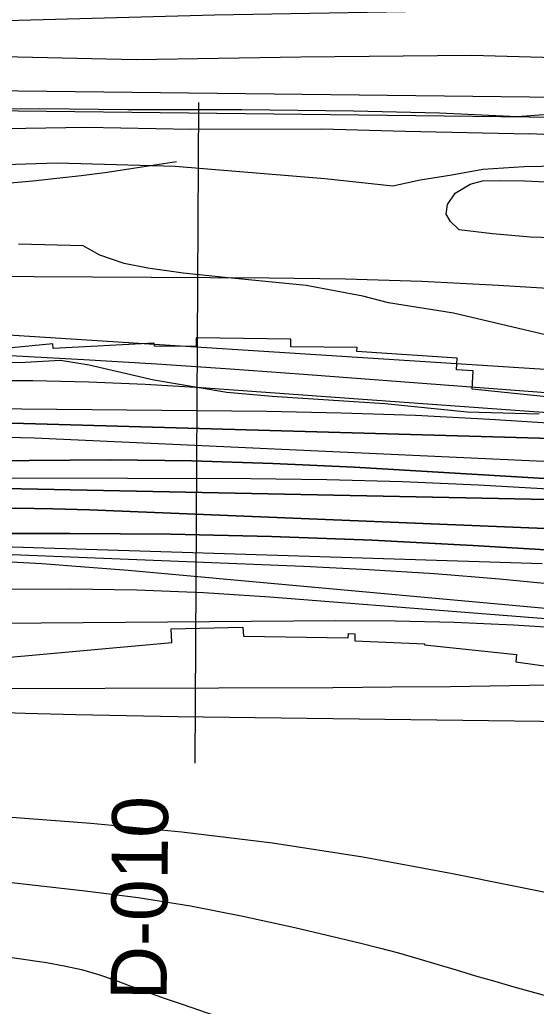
# Model space of a CAD drawing. Extents: x 3477039 to 3515015, y 546746 to 572297.
# Drawn here: x 3495218 to 3495983, y 565048 to 566511 of the extents above; entities that cross this region are included whole.
import ezdxf

# ---------------------------------------------------------------- set-up
doc = ezdxf.new("R2010")
doc.units = 0
for name, color, linetype in [('V-FLOD-BASE', 7, 'Continuous'), ('V-LEVE-TOET', 7, 'Continuous'), ('V-RIVR-EDGE', 7, 'Continuous'), ('V-RIVR-RANG', 7, 'Continuous'), ('V-RIVR-RANG-IDEN', 7, 'Continuous'), ('V-ROAD-CNTR', 7, 'Continuous'), ('V-RRAP-RVMT', 7, 'Continuous'), ('V-SITE-VEGE', 7, 'Continuous'), ('V-SURV-LINE', 7, 'Continuous'), ('V-TOPO-DPTH', 7, 'Continuous'), ('V-TOPO-MAJR', 7, 'Continuous'), ('V-TOPO-MINR', 7, 'Continuous'), ('V-TOPO-WATR', 7, 'Continuous'), ('V-WETL-SWMP', 7, 'Continuous')]:
    doc.layers.add(name, color=color, linetype=linetype)

msp = doc.modelspace()

# ---------------------------------------------------------------- linework, layer by layer
at = {"layer": 'V-FLOD-BASE'}
msp.add_lwpolyline([(3494639.8, 566308.8), (3494681.3, 566333.5), (3494743, 566352.4), (3494831.7, 566366.4), (3494856.4, 566368), (3494919.1, 566360.5), (3494977.8, 566353.6), (3495010.6, 566356.3), (3495078.7, 566362.8), (3495149.8, 566373.4), (3495191.5, 566378.4), (3495247.3, 566379.2), (3495377.5, 566377.6), (3495546.5, 566377.5), (3495712, 566375.7), (3495839.3, 566372.4), (3495954.2, 566367.4), (3496006.8, 566370.9)], dxfattribs=at)
at = {"layer": 'V-LEVE-TOET'}
for points in [[(3496080.2, 566452), (3495886.6, 566457.5), (3495633.7, 566455.3), (3495390.2, 566451.3), (3495170.2, 566456.4), (3495035.8, 566458), (3494947.5, 566457), (3494877.4, 566456.3), (3494775.8, 566444.7), (3494565.5, 566414.6), (3494406.3, 566389.4), (3494203.1, 566361), (3494009.2, 566332.5), (3493874.7, 566309.4), (3493682, 566282.1), (3493457.7, 566250.4), (3493368.4, 566234.6), (3493294.9, 566215.2), (3493192.5, 566183.7)], [(3494244.5, 566253.3), (3494443.1, 566285.8), (3494583.4, 566301.2), (3494606.6, 566302.1), (3494645.7, 566303.7), (3494796.6, 566327.2), (3494845.4, 566333.9), (3494861.8, 566335.5), (3494892.9, 566332.9), (3494949.8, 566323.7), (3494973.8, 566320), (3495001.9, 566318.6), (3495068.3, 566328.1), (3495147.1, 566343.9), (3495170, 566346.7), (3495197, 566349.4), (3495315.5, 566351.5), (3495471, 566348.6), (3495664.6, 566348.9), (3495788.4, 566345.6), (3495972.6, 566341.6)], [(3496555.2, 566271.5), (3496535.5, 566269.3), (3496507.6, 566281.7), (3496474.5, 566296.9), (3496443.6, 566306.7), (3496386.4, 566320.4), (3496328.7, 566329.3), (3496256, 566335.1), (3496175.8, 566338.2), (3496118.1, 566340.7), (3496026.1, 566339.1), (3495972.6, 566341.6)]]:
    msp.add_lwpolyline(points, dxfattribs=at)
at = {"layer": 'V-RIVR-EDGE'}
msp.add_lwpolyline([(3495987, 565925.7), (3495880.4, 565928.5), (3495758.5, 565941), (3495591.3, 565951.8), (3495524.5, 565958.1), (3495416.1, 565976.2), (3495320.5, 565998.5), (3495277.7, 566005.3), (3495225.6, 566002.4), (3495145.9, 566001.4), (3495072.4, 565991.7), (3495002.5, 565983.9), (3494900.7, 565962.7), (3494814.9, 565956.8), (3494768.9, 565943.5), (3494694.8, 565951.6), (3494618.8, 565945.7), (3494578.3, 565921.9), (3494528.1, 565909.7), (3494463.1, 565920.3), (3494433.1, 565913.7), (3494362.5, 565870.9), (3494346.6, 565853.8)], dxfattribs=at)
at = {"layer": 'V-RIVR-RANG'}
msp.add_line((3495482.1, 566388.1), (3495477.1, 565408.1), dxfattribs=at)
at = {"layer": 'V-ROAD-CNTR'}
msp.add_lwpolyline([(3495902.1, 566524.5), (3495505.9, 566517.2), (3495124.7, 566506.9)], dxfattribs=at)
msp.add_lwpolyline([(3495902.1, 566524.5), (3495505.9, 566517.2), (3495124.7, 566506.9)], dxfattribs=at)
at = {"layer": 'V-RRAP-RVMT'}
for points in [[(3496012.1, 565950), (3495887.9, 565962.9), (3495889.1, 565990.2), (3495864.4, 565991.5), (3495865.3, 566008.6), (3495717, 566018.9), (3495717.3, 566024.7), (3495619.1, 566025.4), (3495618.9, 566037), (3495478.8, 566039), (3495478.7, 566026.3), (3495417, 566026.7), (3495416.9, 566031), (3495267.1, 566023.3), (3495266.6, 566030), (3495108.1, 566014.8)], [(3494330.6, 565424.6), (3494453.9, 565441.3), (3494460.1, 565408.4), (3494623, 565435.5), (3494622.5, 565441.1), (3494845.3, 565474.4), (3494845.1, 565483), (3495029.1, 565505.9), (3495024.3, 565557.7), (3495146.4, 565573.9), (3495147.9, 565560.7), (3495442.6, 565587.3), (3495441.7, 565607.6), (3495547.8, 565610), (3495549.1, 565596.7), (3495704, 565594.1), (3495704.5, 565600.4), (3495714.1, 565600), (3495713.8, 565589.7), (3495817.2, 565585)], [(3495817.2, 565585), (3495817, 565583.5), (3495953.6, 565569.2), (3495952.4, 565558.6), (3496110.6, 565536.2)]]:
    msp.add_lwpolyline(points, dxfattribs=at)
at = {"layer": 'V-SITE-VEGE'}
for points in [[(3495164.3, 566295.2), (3495273.1, 566298.5), (3495447.7, 566293.7), (3495669.3, 566275), (3495770.2, 566264.5), (3495810.5, 566273.1), (3495857.6, 566280.7), (3495903.7, 566289.2), (3495964.6, 566292.8), (3496044, 566294.3)], [(3496006.9, 566040.7), (3495860.1, 566075.3), (3495763.8, 566090.8), (3495725.7, 566101), (3495641.7, 566116.4), (3495516.5, 566129.1), (3495459.5, 566134.8), (3495407.2, 566142.2), (3495372, 566149), (3495336.2, 566161.6), (3495311.6, 566175.3), (3495215.7, 566177.8)]]:
    msp.add_lwpolyline(points, dxfattribs=at)
at = {"layer": 'V-SURV-LINE'}
for points in [[(3494962.7, 566408.2), (3496182.8, 566393.8)], [(3496182.5, 566363.8), (3494962.3, 566378.2)]]:
    msp.add_lwpolyline(points, dxfattribs=at)
at = {"layer": 'V-TOPO-DPTH'}
for points in [[(3496218.5, 565911.7), (3495486.1, 565964.9), (3495403.1, 565969.9), (3495320.1, 565973.4), (3495237.1, 565975), (3495154, 565975.1), (3495049.9, 565974), (3495018.8, 565973.1), (3494987.8, 565971.6), (3494956.8, 565969), (3494925.9, 565965.8), (3494648.9, 565931.8), (3494499.1, 565912.1), (3494349.5, 565890.6)], [(3496230.7, 565883.3), (3494996.7, 565918.6), (3494992.9, 565918.7), (3494989, 565918.6), (3494985.2, 565918.4), (3494981.3, 565918.2), (3494928, 565913.4), (3494897.5, 565910.4), (3494867, 565907), (3494836.7, 565902.9), (3494806.4, 565898.3), (3494778.8, 565893.9), (3494734.8, 565886.8), (3494690.7, 565879.9), (3494646.6, 565873.1), (3494602.5, 565866.3), (3494256.1, 565814.1)], [(3494256.1, 565814.1), (3494602.5, 565866.3), (3494646.6, 565873.1), (3494690.7, 565879.9), (3494734.8, 565886.8), (3494778.8, 565893.9), (3494806.4, 565898.3), (3494836.7, 565902.9), (3494867, 565907), (3494897.5, 565910.4), (3494928, 565913.4), (3494981.3, 565918.2), (3494985.2, 565918.4), (3494989, 565918.6), (3494992.9, 565918.7), (3494996.7, 565918.6), (3496230.7, 565883.3)], [(3496202.8, 565817.8), (3495712.9, 565847), (3495592.6, 565852.7), (3495472.3, 565856.7), (3495351.9, 565857.9), (3495231.5, 565857.3), (3495032.8, 565854), (3495011.8, 565853.4), (3494990.7, 565852.4), (3494969.7, 565850.9), (3494948.7, 565849), (3494727.1, 565825.8), (3494595.5, 565811.1), (3494464, 565795.1), (3494332.8, 565777.2)], [(3494332.8, 565777.2), (3494464, 565795.1), (3494595.5, 565811.1), (3494727.1, 565825.8), (3494948.7, 565849), (3494969.7, 565850.9), (3494990.7, 565852.4), (3495011.8, 565853.4), (3495032.8, 565854), (3495231.5, 565857.3), (3495351.9, 565857.9), (3495472.3, 565856.7), (3495592.6, 565852.7), (3495712.9, 565847), (3496202.8, 565817.8)], [(3494307.6, 565736.5), (3494416.3, 565750.6), (3494525.1, 565764.8), (3494633.9, 565779.1), (3494781.7, 565798.6), (3494816.5, 565802.9), (3494851.5, 565806.9), (3494886.4, 565810.5), (3494921.4, 565813.7), (3494983.1, 565818.9), (3494987.3, 565819.2), (3494991.5, 565819.4), (3494995.7, 565819.5), (3494999.9, 565819.4), (3496024.1, 565798.6)], [(3494307.6, 565736.5), (3494416.3, 565750.6), (3494525.1, 565764.8), (3494633.9, 565779.1), (3494781.7, 565798.6), (3494816.5, 565802.9), (3494851.5, 565806.9), (3494886.4, 565810.5), (3494921.4, 565813.7), (3494983.1, 565818.9), (3494987.3, 565819.2), (3494991.5, 565819.4), (3494995.7, 565819.5), (3494999.9, 565819.4), (3496024.1, 565798.6)], [(3496164.7, 565749.3), (3495321.1, 565783.9), (3495266.4, 565785.5), (3495211.6, 565786.3), (3495156.8, 565785.8), (3495102, 565784.5), (3495061.9, 565783.1), (3495027.2, 565781.5), (3494992.5, 565779.4), (3494957.9, 565776.6), (3494923.4, 565773.3), (3494346.6, 565711.7), (3494251.7, 565700.5), (3494156.9, 565688.1), (3494062.4, 565673.7), (3493968, 565658.1), (3493820.9, 565632.1), (3493800.3, 565628.2), (3493779.8, 565623.9), (3493759.5, 565619.1), (3493739.2, 565613.9), (3493100.5, 565400)], [(3493100.5, 565400), (3493739.2, 565613.9), (3493759.5, 565619.1), (3493779.8, 565623.9), (3493800.3, 565628.2), (3493820.9, 565632.1), (3493968, 565658.1), (3494062.4, 565673.7), (3494156.9, 565688.1), (3494251.7, 565700.5), (3494346.6, 565711.7), (3494923.4, 565773.3), (3494957.9, 565776.6), (3494992.5, 565779.4), (3495027.2, 565781.5), (3495061.9, 565783.1), (3495102, 565784.5), (3495156.8, 565785.8), (3495211.6, 565786.3), (3495266.4, 565785.5), (3495321.1, 565783.9), (3496164.7, 565749.3)], [(3496196.7, 565712.7), (3495888.8, 565731.1), (3495739.7, 565738.7), (3495590.5, 565744.5), (3495441.3, 565747.6), (3495292, 565748.8), (3495030.8, 565748.7), (3495012, 565748.5), (3494993.3, 565747.9), (3494974.6, 565746.9), (3494955.9, 565745.6), (3494669, 565721.4), (3494520.7, 565707), (3494372.7, 565689.9), (3494225.3, 565668.9)], [(3494225.3, 565668.9), (3494372.7, 565689.9), (3494520.7, 565707), (3494669, 565721.4), (3494955.9, 565745.6), (3494974.6, 565746.9), (3494993.3, 565747.9), (3495012, 565748.5), (3495030.8, 565748.7), (3495292, 565748.8), (3495441.3, 565747.6), (3495590.5, 565744.5), (3495739.7, 565738.7), (3495888.8, 565731.1), (3496196.7, 565712.7)]]:
    msp.add_lwpolyline(points, dxfattribs=at)
at = {"layer": 'V-TOPO-MAJR'}
for points in [[(3495991.4, 565703.7), (3495945.2, 565705.5), (3495017.7, 565734.5), (3495005.6, 565734.7), (3494993.6, 565734.6), (3494981.6, 565734.1), (3494969.6, 565733.4), (3494776.6, 565718.1), (3494668.3, 565708), (3494560.2, 565695.9), (3494452.6, 565680.8), (3494345.1, 565663.7)], [(3496030.1, 565524.5), (3495942.9, 565522.9), (3495855.7, 565521.6), (3495768.5, 565520.8), (3495681.3, 565520.2), (3495005.6, 565517.9)], [(3495150.2, 565484.9), (3495225.4, 565482.4), (3495300.7, 565480.2), (3495375.9, 565478.7), (3495451.2, 565477.4), (3496181.2, 565468.2)]]:
    msp.add_lwpolyline(points, dxfattribs=at)
at = {"layer": 'V-TOPO-MINR'}
for points in [[(3495449.9, 566299.8), (3495379.1, 566288.9), (3495343.7, 566283.7), (3495308.3, 566279), (3495272.7, 566275), (3495237.1, 566271.5), (3495018.1, 566251.8)], [(3495063.4, 566131), (3495586.6, 566128.1), (3495700, 566126.3), (3495813.3, 566122.9), (3495926.5, 566117.2), (3496039.7, 566110)], [(3496018.5, 565990.4), (3495030.9, 566053.6), (3495008.3, 566054.6), (3494985.6, 566054.9), (3494963, 566054.2), (3494940.3, 566052.8), (3493766.7, 565918.3), (3493750.4, 565915.4), (3493734.1, 565912.4), (3493717.8, 565909.3), (3493701.5, 565906.2), (3492483.3, 565669.6)], [(3496192.9, 565942.6), (3495637.8, 565984.6), (3495529.3, 565992.4), (3495420.8, 565999.8), (3495312.3, 566006.3), (3495203.7, 566012.4), (3494999, 566023.1), (3494992.7, 566023.3), (3494986.4, 566023.3), (3494980.1, 566023.1), (3494973.8, 566022.7), (3494115.1, 565898.8), (3494041.3, 565886.2), (3493967.6, 565873), (3493894, 565859.4), (3493797, 565840.9), (3493772, 565836), (3493747, 565830.8), (3493722.1, 565825.3), (3493697.2, 565819.5), (3492747.2, 565579.2)], [(3496218.5, 565911.7), (3495486.1, 565964.9), (3495403.1, 565969.9), (3495320.1, 565973.4), (3495237.1, 565975), (3495154, 565975.1), (3495049.9, 565974), (3495018.8, 565973.1), (3494987.8, 565971.6), (3494956.8, 565969), (3494925.9, 565965.8), (3494648.9, 565931.8), (3494499.1, 565912.1), (3494349.5, 565890.6)], [(3496024.2, 565910.7), (3495914.1, 565917.9), (3495804, 565923.7), (3495693.7, 565927.3), (3495583.4, 565929.5), (3495012.8, 565935.1), (3495000.7, 565935), (3494988.6, 565934.7), (3494976.6, 565934.1), (3494964.5, 565933.2), (3494799.3, 565918.5), (3494704.8, 565908.9), (3494610.4, 565897.8), (3494516.4, 565884.4), (3494422.6, 565869.4), (3494271.3, 565843.4)], [(3496177.3, 565847), (3495239.5, 565890.1), (3495197.9, 565891.4), (3495156.3, 565892.1), (3495114.7, 565891.6), (3495073.1, 565890.5), (3495065.6, 565890.2), (3495027.8, 565888.1), (3494990, 565885.4), (3494952.2, 565881.6), (3494914.6, 565877.2), (3494531.1, 565827.1), (3494403.3, 565809.7), (3494275.6, 565791.3)], [(3496202.8, 565817.8), (3495712.9, 565847), (3495592.6, 565852.7), (3495472.3, 565856.7), (3495351.9, 565857.9), (3495231.5, 565857.3), (3495032.8, 565854), (3495011.8, 565853.4), (3494990.7, 565852.4), (3494969.7, 565850.9), (3494948.7, 565849), (3494727.1, 565825.8), (3494595.5, 565811.1), (3494464, 565795.1), (3494332.8, 565777.2)], [(3496009.4, 565814.1), (3495897.1, 565820.5), (3495784.7, 565825.5), (3495672.3, 565828.3), (3495559.8, 565829.7), (3495011.4, 565831.3), (3495001.3, 565831.2), (3494991.2, 565831), (3494981.1, 565830.4), (3494971, 565829.7), (3494823.3, 565817.2), (3494739.4, 565809.4), (3494655.6, 565800.7), (3494572, 565790.8), (3494488.4, 565779.9), (3493837.2, 565689.8)], [(3496024.1, 565798.6), (3494999.9, 565819.4), (3494995.7, 565819.5), (3494991.5, 565819.4), (3494987.3, 565819.2), (3494983.1, 565818.9), (3494921.4, 565813.7), (3494886.4, 565810.5), (3494851.5, 565806.9), (3494816.5, 565802.9), (3494781.7, 565798.6), (3494633.9, 565779.1), (3494525.1, 565764.8), (3494416.3, 565750.6), (3494307.6, 565736.5)], [(3496164.7, 565749.3), (3495321.1, 565783.9), (3495266.4, 565785.5), (3495211.6, 565786.3), (3495156.8, 565785.8), (3495102, 565784.5), (3495061.9, 565783.1), (3495027.2, 565781.5), (3494992.5, 565779.4), (3494957.9, 565776.6), (3494923.4, 565773.3), (3494346.6, 565711.7), (3494251.7, 565700.5), (3494156.9, 565688.1), (3494062.4, 565673.7), (3493968, 565658.1), (3493820.9, 565632.1), (3493800.3, 565628.2), (3493779.8, 565623.9), (3493759.5, 565619.1), (3493739.2, 565613.9), (3493100.5, 565400)], [(3496196.7, 565712.7), (3495888.8, 565731.1), (3495739.7, 565738.7), (3495590.5, 565744.5), (3495441.3, 565747.6), (3495292, 565748.8), (3495030.8, 565748.7), (3495012, 565748.5), (3494993.3, 565747.9), (3494974.6, 565746.9), (3494955.9, 565745.6), (3494669, 565721.4), (3494520.7, 565707), (3494372.7, 565689.9), (3494225.3, 565668.9)], [(3496180.4, 565620.9), (3495378, 565693.8), (3495314.1, 565699.1), (3495250.2, 565703.8), (3495186.2, 565707.5), (3495122.2, 565710.5), (3494998.5, 565715.5), (3494996.3, 565715.5), (3494991.8, 565715.4), (3494989.6, 565715.3), (3494953.9, 565712.5), (3494933.8, 565710.6), (3494913.8, 565708.3), (3494893.9, 565705.3), (3494874, 565702), (3494871.5, 565701.5), (3494850.4, 565697.5), (3494829.4, 565693.4), (3494808.4, 565689.1), (3494787.4, 565684.6), (3494609.5, 565645.5), (3494499.5, 565622), (3494389.4, 565599.1), (3494279, 565577.3)], [(3496024.9, 565671.5), (3495928.3, 565680.9), (3495831.7, 565689), (3495734.9, 565695.1), (3495638, 565700), (3495008.1, 565724.9), (3495001, 565725.1), (3494993.8, 565725), (3494986.7, 565724.8), (3494979.6, 565724.3), (3494865.2, 565715.3), (3494801, 565709.2), (3494737, 565702), (3494673.2, 565692.8), (3494609.6, 565682.4), (3494592.2, 565679.3), (3494520, 565666), (3494447.9, 565652.4), (3494376, 565638.1), (3494304.1, 565623.4)], [(3496191.5, 565607.1), (3495588.2, 565654.3), (3495489.6, 565660.6), (3495390.8, 565664.9), (3495292, 565666.3), (3495193.2, 565665.8), (3495046.1, 565662.9), (3495020.8, 565661.8), (3494995.6, 565659.9), (3494970.5, 565656.8), (3494945.5, 565653), (3494816.2, 565629.9), (3494743, 565616.6), (3494669.8, 565603), (3494596.7, 565589), (3494523.6, 565574.7), (3494493.2, 565568.6), (3494435.4, 565556.9), (3494377.8, 565544.7), (3494320.2, 565532.1)], [(3496036.6, 565607.6), (3495949, 565613), (3495861.3, 565617), (3495773.6, 565618.8), (3495685.9, 565619.2), (3494999.3, 565614)], [(3495035.3, 565340.9), (3495322.9, 565319.1), (3495457.7, 565306.3), (3495592, 565290.2), (3495725.6, 565269.2), (3495858.8, 565244.8), (3496116.3, 565192.7)], [(3494329.9, 565235.4), (3494450.7, 565240.9), (3494571.6, 565244.7), (3494963.1, 565252.9), (3494984.3, 565253), (3495005.5, 565252.4), (3495026.7, 565251), (3495047.8, 565249.1), (3495314.5, 565219), (3495392.8, 565208.8), (3495470.7, 565196.6), (3495548.1, 565181.6), (3495625.2, 565164.6), (3495721, 565141.7), (3495749.8, 565134.5), (3495778.5, 565126.9), (3495807.1, 565118.8), (3495835.6, 565110.2), (3495864, 565101.6), (3495892.5, 565093.1), (3495921.1, 565084.8), (3495949.7, 565076.8), (3496086.1, 565039.2)], [(3493985.8, 564991.1), (3494971.3, 565145.9), (3494989.7, 565146.5), (3495008.1, 565146.4), (3495026.5, 565145.1), (3495044.8, 565143.1), (3495257.4, 565112.5), (3495283.3, 565107.9), (3495308.9, 565102.2), (3495334, 565094.9), (3495358.9, 565086.4), (3495383.7, 565077.3), (3495408.4, 565068.2), (3495433.2, 565059.4), (3495458.1, 565050.7), (3495508.2, 565033.4)]]:
    msp.add_lwpolyline(points, dxfattribs=at)
at = {"layer": 'V-TOPO-WATR'}
msp.add_lwpolyline([(3496230.7, 565883.3), (3494996.7, 565918.6), (3494992.9, 565918.7), (3494989, 565918.6), (3494985.2, 565918.4), (3494981.3, 565918.2), (3494928, 565913.4), (3494897.5, 565910.4), (3494867, 565907), (3494836.7, 565902.9), (3494806.4, 565898.3), (3494778.8, 565893.9), (3494734.8, 565886.8), (3494690.7, 565879.9), (3494646.6, 565873.1), (3494602.5, 565866.3), (3494256.1, 565814.1)], dxfattribs=at)
at = {"layer": 'V-WETL-SWMP'}
msp.add_lwpolyline([(3496021.4, 566186.8), (3495974.2, 566188.2), (3495917.9, 566193), (3495868.3, 566199.2), (3495855.8, 566211.4), (3495849.1, 566222.2), (3495851.1, 566236.7), (3495862.4, 566253.7), (3495884.9, 566266.6), (3495902.9, 566271.8), (3495927.7, 566272.1), (3495965.6, 566271.9), (3496017.2, 566269.2)], dxfattribs=at)

# ---------------------------------------------------------------- texts
at = {"layer": 'V-RIVR-RANG-IDEN'}
msp.add_text('D-010', height=83, rotation=89.5653, dxfattribs=at).set_placement((3495435.2, 565056.7))

doc.saveas('drawing.dxf')
